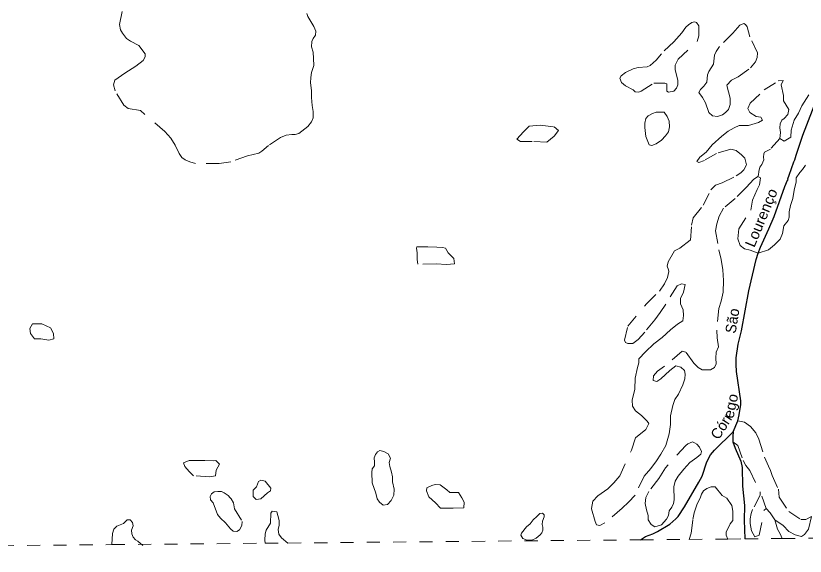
# Model space of a CAD drawing. Extents: x 344.9 to 371, y 7566.4 to 7594.3.
# Drawn here: x 353.71 to 359.71, y 7566.38 to 7570.5 of the extents above; entities that cross this region are included whole.
import ezdxf
from ezdxf.enums import TextEntityAlignment as Align

# ---------------------------------------------------------------- set-up
doc = ezdxf.new("R2010")
doc.units = 0
doc.header["$LTSCALE"] = 0.04
doc.linetypes.add('SHORT_DASHED', pattern=[2.7, 1.5, -1.2])
for name, color, linetype, lineweight in [('17', 7, 'SHORT_DASHED', 13), ('21', 7, 'SHORT_DASHED', 13), ('53', 7, 'SHORT_DASHED', 13), ('7', 7, 'Continuous', 25)]:
    doc.layers.add(name, color=color, linetype=linetype, lineweight=lineweight)
doc.layers.add('61', color=7, linetype='Continuous')

msp = doc.modelspace()

# ---------------------------------------------------------------- linework, layer by layer
at = {"layer": '17'}
msp.add_line((359.416, 7566.7457), (359.3694, 7566.873), dxfattribs=at)
for points in [[(359.5193, 7569.5618), (359.4485, 7569.4815), (359.4019, 7569.4581), (359.3972, 7569.4461), (359.3945, 7569.4193), (359.3963, 7569.3996), (359.382, 7569.3639), (359.3677, 7569.3424), (359.3587, 7569.3111), (359.3569, 7569.2852), (359.3512, 7569.2717)], [(359.7609, 7566.6839), (359.7358, 7566.5883), (359.7075, 7566.5486), (359.6848, 7566.5316), (359.6367, 7566.5458), (359.5885, 7566.5713), (359.5432, 7566.6166), (359.4808, 7566.6583)]]:
    msp.add_lwpolyline(points, dxfattribs=at)
at = {"layer": '21'}
msp.add_line((359.5232, 7569.6072), (359.5193, 7569.5618), dxfattribs=at)
for points in [[(355.9201, 7570.5139), (355.9278, 7570.4906), (355.9744, 7570.4149), (355.9899, 7570.3781), (355.986, 7570.347), (355.9686, 7570.3218), (355.9589, 7570.3004), (355.955, 7570.2597), (355.9686, 7570.2189), (355.9744, 7570.1161), (355.957, 7570.0638), (355.9511, 7570.025), (355.9492, 7569.9842), (355.955, 7569.926), (355.955, 7569.8737), (355.9608, 7569.8116), (355.9686, 7569.767), (355.9686, 7569.7185), (355.957, 7569.6894), (355.9279, 7569.6525), (355.8603, 7569.5997), (355.8328, 7569.5924), (355.8057, 7569.5924), (355.763, 7569.5866), (355.7203, 7569.5691), (355.6291, 7569.509), (355.5787, 7569.4643), (355.5554, 7569.4508), (355.4682, 7569.4304), (355.3421, 7569.3838), (355.2548, 7569.3722), (355.0744, 7569.3722), (355.0318, 7569.3829), (354.9949, 7569.3984), (354.9697, 7569.4158), (354.9503, 7569.4469), (354.9193, 7569.5109), (354.8863, 7569.5652), (354.8417, 7569.6156), (354.6555, 7569.7738), (354.5624, 7569.7893), (354.5275, 7569.8165), (354.4616, 7569.9251), (354.4499, 7569.9697), (354.4596, 7570.0066), (354.5353, 7570.0589), (354.6187, 7570.1113), (354.6749, 7570.1559), (354.6905, 7570.1831), (354.6905, 7570.2064), (354.644, 7570.2694), (354.58, 7570.3024), (354.5489, 7570.3238), (354.5179, 7570.3626), (354.5024, 7570.3897), (354.4966, 7570.4304), (354.5257, 7570.5701)], [(358.4353, 7567.8184), (358.4451, 7567.854), (358.4471, 7567.8836), (358.4965, 7567.9389), (358.5597, 7567.9981), (358.6229, 7568.0475), (358.686, 7568.1047), (358.7394, 7568.1482), (358.7808, 7568.1739), (358.7867, 7568.2133), (358.7828, 7568.2577), (358.763, 7568.3031), (358.763, 7568.3426), (358.7867, 7568.392), (358.7985, 7568.4493), (358.7709, 7568.4552), (358.7373, 7568.4414), (358.6505, 7568.3012), (358.609, 7568.238), (358.5675, 7568.1827), (358.4925, 7568.0879), (358.4412, 7568.0326), (358.4017, 7568.001), (358.3622, 7568.001), (358.3444, 7568.0089), (358.3365, 7568.0257), (358.3622, 7568.1323), (358.5043, 7568.3041), (358.6031, 7568.4008), (358.6406, 7568.4542), (358.6643, 7568.5035), (358.6742, 7568.5499), (358.6728, 7568.562), (358.6623, 7568.5894), (358.6702, 7568.623), (358.7176, 7568.7059), (358.7571, 7568.7276), (358.8381, 7568.7888), (358.8479, 7568.9014), (358.8598, 7568.9586), (358.9368, 7569.0534), (358.9941, 7569.1718), (359.0296, 7569.2074), (359.079, 7569.2251), (359.1876, 7569.2765), (359.2212, 7569.3002), (359.2449, 7569.3239), (359.2646, 7569.3614), (359.2528, 7569.4107), (359.2271, 7569.4384), (359.1876, 7569.47), (359.1461, 7569.4798), (359.0375, 7569.4483), (358.9447, 7569.3949), (358.9033, 7569.3791), (358.8875, 7569.387), (358.9112, 7569.4206), (358.9585, 7569.4581), (359.004, 7569.5134), (359.077, 7569.5805), (359.1264, 7569.6181), (359.1718, 7569.6437), (359.2093, 7569.6595), (359.2804, 7569.6605), (359.3554, 7569.6823), (359.387, 7569.7), (359.3732, 7569.7237), (359.3376, 7569.7296), (359.2902, 7569.7593), (359.2744, 7569.7889), (359.2942, 7569.8303), (359.4008, 7569.933), (359.5074, 7570.0002), (359.545, 7570.0021), (359.5292, 7569.9705), (359.5469, 7569.8896), (359.5469, 7569.8481), (359.5864, 7569.783), (359.5785, 7569.7454), (359.5509, 7569.7139), (359.5351, 7569.702), (359.5213, 7569.6724), (359.5193, 7569.6428), (359.5232, 7569.6072)], [(359.5193, 7569.5618), (359.5509, 7569.5401), (359.6022, 7569.5717), (359.6062, 7569.625), (359.6279, 7569.702), (359.6615, 7569.7553), (359.6871, 7569.8106), (359.7385, 7569.8935)], [(359.7136, 7569.3595), (359.6914, 7569.3262), (359.6705, 7569.3028), (359.6434, 7569.261), (359.6422, 7569.2321), (359.6274, 7569.1693), (359.6176, 7569.1052), (359.5991, 7569.0523), (359.5905, 7569.0042), (359.5905, 7568.9624), (359.5832, 7568.9372), (359.5499, 7568.8977), (359.5404, 7568.839), (359.5207, 7568.7946), (359.4788, 7568.7528), (359.432, 7568.7146), (359.3552, 7568.6879)], [(359.3512, 7569.2717), (359.3176, 7569.25), (359.2663, 7569.1907), (359.1794, 7569.1058), (359.0905, 7569.0308), (359.057, 7568.9715), (359.0392, 7568.9133), (359.0294, 7568.8599), (359.055, 7568.7138), (359.0728, 7568.6408), (359.0846, 7568.5618), (359.0906, 7568.4808), (359.0867, 7568.3929), (359.0728, 7568.3238), (359.0551, 7568.2685), (359.0393, 7568.1027), (359.0432, 7568.0454), (359.0531, 7567.9763), (359.0353, 7567.9358), (359.0314, 7567.8884), (359.0334, 7567.847), (359.0215, 7567.8174), (358.9919, 7567.7996), (358.9287, 7567.7996), (358.8971, 7567.8174), (358.8655, 7567.8509), (358.8043, 7567.9358), (358.7767, 7567.9417), (358.6404, 7567.8292), (358.5891, 7567.7917), (358.5575, 7567.7542), (358.5556, 7567.7206), (358.5832, 7567.7127), (358.6128, 7567.7334), (358.6819, 7567.7966), (358.7273, 7567.8302), (358.7668, 7567.8223), (358.7925, 7567.7966), (358.7984, 7567.769), (358.7965, 7567.7334), (358.7807, 7567.686), (358.7491, 7567.615), (358.7194, 7567.5755), (358.7056, 7567.5301), (358.6879, 7567.4511), (358.6859, 7567.3839), (358.676, 7567.3148), (358.6523, 7567.226), (358.6128, 7567.1579), (358.5812, 7567.1085), (358.5378, 7567.0493), (358.4864, 7566.992), (358.4173, 7566.8479), (358.368, 7566.7926), (358.3206, 7566.7472), (358.1883, 7566.6366), (358.1508, 7566.6169), (358.1232, 7566.6209), (358.1133, 7566.6465), (358.0857, 7566.7452), (358.0975, 7566.8015), (358.1351, 7566.841), (358.2101, 7566.8963), (358.2555, 7566.9397), (358.3009, 7566.993), (358.3898, 7567.1905), (358.4214, 7567.2833), (358.5004, 7567.3475), (358.5221, 7567.3929), (358.5103, 7567.4107), (358.4668, 7567.4521), (358.4214, 7567.4877), (358.3977, 7567.5252), (358.3957, 7567.5706), (358.4155, 7567.6535), (358.4175, 7567.7365), (358.4353, 7567.8184)], [(359.3552, 7568.6879), (359.292, 7568.7109), (359.2505, 7568.7207), (359.2169, 7568.7484), (359.1991, 7568.7978), (359.207, 7568.8728), (359.2979, 7569.017), (359.3117, 7569.092), (359.3453, 7569.173), (359.365, 7569.2085), (359.3729, 7569.2618), (359.3512, 7569.2717)], [(359.1987, 7567.4136), (359.2503, 7567.4023), (359.2955, 7567.3691), (359.3362, 7567.3225), (359.3603, 7567.2727), (359.4025, 7567.1357), (359.4446, 7567.0423), (359.4597, 7566.9971), (359.5079, 7566.8932), (359.5139, 7566.8315), (359.5877, 7566.7215), (359.6781, 7566.6613), (359.7158, 7566.6613), (359.7609, 7566.6839)], [(359.1624, 7567.2535), (359.1992, 7567.2262), (359.2399, 7567.1117), (359.2609, 7567.0726), (359.2896, 7567.0334), (359.3694, 7566.873)], [(358.8284, 7566.5104), (358.8453, 7566.557), (358.8574, 7566.6609), (358.8664, 7566.7121), (358.8905, 7566.7814), (358.9116, 7566.8251), (358.9222, 7566.8552), (358.9387, 7566.8808), (358.9643, 7566.8974), (358.9959, 7566.911), (359.026, 7566.911), (359.0803, 7566.8432), (359.1149, 7566.8236), (359.1526, 7566.7679), (359.1616, 7566.7257), (359.1601, 7566.655), (359.1405, 7566.6293), (359.1104, 7566.5661), (359.1104, 7566.542), (359.123, 7566.513)], [(359.3694, 7566.873), (359.3694, 7566.8474), (359.3121, 7566.7375), (359.3016, 7566.7073), (359.2925, 7566.6667), (359.2925, 7566.6305), (359.3031, 7566.5748), (359.3286, 7566.5296), (359.3618, 7566.5416), (359.3979, 7566.7291), (359.416, 7566.7457)], [(359.416, 7566.7457), (359.4461, 7566.7126), (359.4808, 7566.6583)], [(355.6028, 7566.481), (355.601, 7566.5044), (355.6039, 7566.5524), (355.6116, 7566.5803), (355.6433, 7566.6341), (355.6471, 7566.711), (355.6567, 7566.724), (355.6923, 7566.7201), (355.7009, 7566.6913), (355.7105, 7566.6529), (355.7105, 7566.6192), (355.7038, 7566.5856), (355.7067, 7566.551), (355.7278, 7566.5231), (355.7769, 7566.4826)], [(354.437, 7566.4703), (354.4418, 7566.5562), (354.4514, 7566.5869), (354.4754, 7566.61), (354.5254, 7566.6302), (354.5542, 7566.659), (354.5773, 7566.66), (354.5946, 7566.6398), (354.5984, 7566.6138), (354.5879, 7566.5802), (354.5888, 7566.5523), (354.6004, 7566.5264), (354.6167, 7566.5071), (354.634, 7566.4975), (354.6725, 7566.4649)], [(359.4808, 7566.6583), (359.5003, 7566.5891), (359.5214, 7566.5529), (359.5359, 7566.5166)]]:
    msp.add_lwpolyline(points, dxfattribs=at)
for points in [[(358.7734, 7570.3671), (358.7118, 7570.2974), (358.6189, 7570.2071), (358.5778, 7570.1579), (358.5327, 7570.1183), (358.5109, 7570.1073), (358.4411, 7570.1032), (358.4042, 7570.0923), (358.344, 7570.0636), (358.3112, 7570.0376), (358.3016, 7570.0205), (358.3139, 7569.9891), (358.3454, 7569.9617), (358.4028, 7569.9317), (358.4192, 7569.918), (358.4466, 7569.9152), (358.463, 7569.9221), (358.5614, 7569.9822), (358.6448, 7569.9836), (358.6585, 7569.9774), (358.6585, 7569.9214), (358.6721, 7569.9146), (358.7118, 7569.9214), (358.7323, 7569.9446), (358.7419, 7569.9692), (358.7419, 7570.0048), (358.7227, 7570.0841), (358.7227, 7570.1196), (358.7446, 7570.1661), (358.8909, 7570.3007), (358.9032, 7570.3431), (358.9032, 7570.4197), (358.8841, 7570.4457), (358.869, 7570.4484), (358.8499, 7570.4443), (358.8253, 7570.4279), (358.8034, 7570.4087)], [(359.1623, 7570.3621), (359.059, 7570.2618), (359.0347, 7570.2238), (359.021, 7570.1949), (359.0134, 7570.1281), (358.9784, 7570.0718), (358.9678, 7570.046), (358.9648, 7569.9913), (358.9405, 7569.9594), (358.9146, 7569.9351), (358.9025, 7569.9123), (358.9313, 7569.8743), (358.9526, 7569.8333), (358.98, 7569.7603), (359.0058, 7569.733), (359.0438, 7569.7284), (359.0818, 7569.7421), (359.1061, 7569.7603), (359.1289, 7569.7831), (359.1411, 7569.8211), (359.1411, 7569.8682), (359.1152, 7569.967), (359.1517, 7570.005), (359.2018, 7570.0308), (359.2961, 7570.0992), (359.334, 7570.1463), (359.3462, 7570.1782), (359.3477, 7570.2132), (359.2915, 7570.3347), (359.2702, 7570.4122), (359.258, 7570.4297), (359.2444, 7570.4373), (359.2155, 7570.4236)], [(358.577, 7569.7632), (358.5504, 7569.7524), (358.5178, 7569.7336), (358.5, 7569.7139), (358.4921, 7569.6793), (358.4921, 7569.6447), (358.5, 7569.5756), (358.5257, 7569.5134), (358.5445, 7569.5075), (358.578, 7569.5223), (358.6175, 7569.55), (358.6501, 7569.5816), (358.6708, 7569.6132), (358.6797, 7569.6497), (358.6768, 7569.6931), (358.661, 7569.7287), (358.6383, 7569.7612)], [(357.5179, 7569.5558), (357.5681, 7569.6118), (357.6128, 7569.6566), (357.6966, 7569.6622), (357.8026, 7569.651), (357.8361, 7569.623), (357.8026, 7569.5782), (357.7468, 7569.5334), (357.6351, 7569.539), (357.5458, 7569.539)], [(356.7603, 7568.6409), (356.7603, 7568.692), (356.755, 7568.7264), (356.7585, 7568.737), (356.8421, 7568.7362), (356.909, 7568.7353), (356.9539, 7568.7317), (356.9759, 7568.7273), (356.997, 7568.692), (357.0384, 7568.6488), (357.0428, 7568.6065), (356.9821, 7568.6021), (356.9037, 7568.6065), (356.7647, 7568.6047)], [(353.818, 7568.0762), (353.8125, 7568.1154), (353.8348, 7568.1517), (353.9046, 7568.1517), (353.9716, 7568.121), (353.9939, 7568.0762), (353.9967, 7568.037), (353.9576, 7568.0258), (353.8962, 7568.037), (353.8488, 7568.037)], [(358.8035, 7567.225), (358.6499, 7567.0548), (358.5987, 7566.9735), (358.5219, 7566.8741), (358.4993, 7566.8289), (358.4933, 7566.7837), (358.5038, 7566.7355), (358.5174, 7566.6934), (358.5174, 7566.6602), (358.54, 7566.6241), (358.5671, 7566.606), (358.6198, 7566.6211), (358.6559, 7566.6632), (358.6725, 7566.6919), (358.677, 7566.7265), (358.6966, 7566.7551), (358.7102, 7566.7837), (358.7147, 7566.8108), (358.7132, 7566.9103), (358.7237, 7566.9539), (358.7463, 7566.9916), (358.7885, 7567.0458), (358.8352, 7567.0955), (358.8879, 7567.1332), (358.918, 7567.1588), (358.924, 7567.1799), (358.909, 7567.2115), (358.8879, 7567.2356), (358.8698, 7567.2461), (358.8547, 7567.2522), (358.8186, 7567.2371)], [(356.4582, 7567.1775), (356.4421, 7567.1558), (356.4327, 7567.1302), (356.4364, 7567.099), (356.4346, 7567.0697), (356.4185, 7567.0479), (356.4147, 7567.0186), (356.4175, 7566.9401), (356.445, 7566.8617), (356.4563, 7566.82), (356.4724, 7566.7926), (356.5017, 7566.7699), (356.5338, 7566.7747), (356.5622, 7566.8059), (356.583, 7566.8465), (356.5859, 7566.8929), (356.5717, 7566.9487), (356.5726, 7566.9874), (356.566, 7567.0215), (356.5509, 7567.064), (356.5461, 7567.0943), (356.5565, 7567.1293), (356.5395, 7567.1605), (356.5055, 7567.1794), (356.4771, 7567.187)], [(355.025, 7567.0283), (354.9929, 7567.0658), (354.9822, 7567.0935), (355.025, 7567.1114), (355.0963, 7567.1114), (355.1444, 7567.1114), (355.2086, 7567.1078), (355.2291, 7567.1105), (355.2576, 7567.0819), (355.2318, 7567.0381), (355.2255, 7566.9935), (355.1792, 7566.9863), (355.058, 7566.9944)], [(355.6221, 7566.8659), (355.5703, 7566.8178), (355.5357, 7566.815), (355.5116, 7566.8371), (355.5126, 7566.8842), (355.5385, 7566.9101), (355.5539, 7566.9505), (355.5703, 7566.962), (355.6049, 7566.9543), (355.6462, 7566.9005), (355.6452, 7566.8794)], [(356.8999, 7566.7895), (356.8497, 7566.8351), (356.8298, 7566.8788), (356.8326, 7566.9025), (356.8715, 7566.9196), (356.897, 7566.9282), (356.9359, 7566.9263), (356.9852, 7566.8873), (357.0089, 7566.8674), (357.0733, 7566.8664), (357.0989, 7566.8275), (357.1179, 7566.7933), (357.116, 7566.7505), (357.0345, 7566.7486), (356.9368, 7566.7467)], [(355.3381, 7566.826), (355.3445, 7566.8198), (355.3621, 7566.7885), (355.3717, 7566.7423), (355.4294, 7566.6462), (355.4275, 7566.6154), (355.4092, 7566.5818), (355.3871, 7566.5693), (355.3612, 7566.5741), (355.341, 7566.5895), (355.3025, 7566.6356), (355.2631, 7566.6722), (355.24, 7566.6991), (355.2074, 7566.7875), (355.1881, 7566.8115), (355.1843, 7566.8375), (355.1949, 7566.8558), (355.2151, 7566.8711), (355.2429, 7566.875), (355.2718, 7566.875), (355.2929, 7566.8644), (355.3218, 7566.8442)], [(357.6714, 7566.6852), (357.6434, 7566.6594), (357.6199, 7566.6299), (357.5927, 7566.605), (357.5526, 7566.5581), (357.548, 7566.5414), (357.5632, 7566.5172), (357.5965, 7566.5051), (357.6335, 7566.5044), (357.6653, 7566.5187), (357.6963, 7566.5452), (357.7077, 7566.5596), (357.716, 7566.5808), (357.7168, 7566.6035), (357.7115, 7566.6246), (357.713, 7566.6496), (357.7273, 7566.6829), (357.7251, 7566.698), (357.7122, 7566.7109), (357.6925, 7566.7086)]]:
    msp.add_lwpolyline(points, close=True, dxfattribs=at)
at = {"layer": '53'}
msp.add_lwpolyline([(345.1495, 7566.3822), (350.2712, 7566.4313), (351.2121, 7566.4404), (351.9925, 7566.4478), (354.437, 7566.4703), (355.6028, 7566.481), (355.7769, 7566.4826), (358.4581, 7566.5071), (358.8284, 7566.5104), (359.123, 7566.513), (359.2531, 7566.5141), (359.5359, 7566.5166), (359.9555, 7566.5203), (360.3174, 7566.5235), (360.3928, 7566.5242), (360.5559, 7566.5256), (361.4062, 7566.5331)], dxfattribs=at)
at = {"layer": '7'}
for points in [[(359.5577, 7569.1956), (359.5767, 7569.2448), (359.5815, 7569.248), (359.5799, 7569.2536), (359.5886, 7569.283), (359.6252, 7569.383), (359.6339, 7569.3989), (359.6426, 7569.4338), (359.6935, 7569.5863), (359.8713, 7570.0469), (359.911, 7570.1342), (359.9753, 7570.2502), (360.0571, 7570.3581), (360.1127, 7570.4423), (360.1989, 7570.5544), (360.257, 7570.6072), (360.3498, 7570.6773), (360.4323, 7570.7569), (360.5342, 7570.8612), (360.6794, 7571.0184), (360.7818, 7571.1194)], [(359.3552, 7568.6879), (359.3709, 7568.7352), (359.4364, 7568.8729), (359.4752, 7568.9675), (359.5577, 7569.1956)], [(359.1987, 7567.4136), (359.2106, 7567.4573), (359.221, 7567.5376), (359.221, 7567.5661), (359.1893, 7567.7887), (359.1861, 7567.8411), (359.1879, 7567.893), (359.2027, 7567.995), (359.2267, 7568.0984), (359.282, 7568.4031), (359.3395, 7568.6406), (359.3552, 7568.6879)], [(358.4581, 7566.5071), (358.4961, 7566.5325), (358.5524, 7566.5525), (358.5888, 7566.5703), (358.6825, 7566.6268), (358.7268, 7566.6658), (358.7448, 7566.6857), (358.7942, 7566.7577), (358.9026, 7566.9454), (358.9271, 7566.9927), (358.964, 7567.1007), (358.9903, 7567.1536), (359.0221, 7567.1889), (359.1638, 7567.3295), (359.1987, 7567.4136)], [(359.1638, 7567.3295), (359.161, 7567.2967), (359.1624, 7567.2535)], [(359.1624, 7567.2535), (359.1795, 7567.2039), (359.2229, 7567.1051), (359.2321, 7567.0578), (359.2344, 7566.9159), (359.2496, 7566.768), (359.2464, 7566.6561), (359.2531, 7566.5141)]]:
    msp.add_lwpolyline(points, dxfattribs=at)

# ---------------------------------------------------------------- texts
at = {"layer": '61', "width": 1.05}
for s, rotation, p in [('Lourenço', 67.482, (359.4144, 7568.9433)), ('ego', 78.169, (359.1841, 7567.5174))]:
    msp.add_text(s, height=0.08, rotation=rotation, dxfattribs=at).set_placement(p, align=Align.CENTER)
at = {"layer": '61'}
for s, rotation, p in [('São', 80.854, (359.1971, 7568.1676)), ('Córr', 57.653, (359.1095, 7567.3507))]:
    msp.add_text(s, height=0.08, rotation=rotation, dxfattribs=at).set_placement(p, align=Align.CENTER)

doc.saveas('drawing.dxf')
